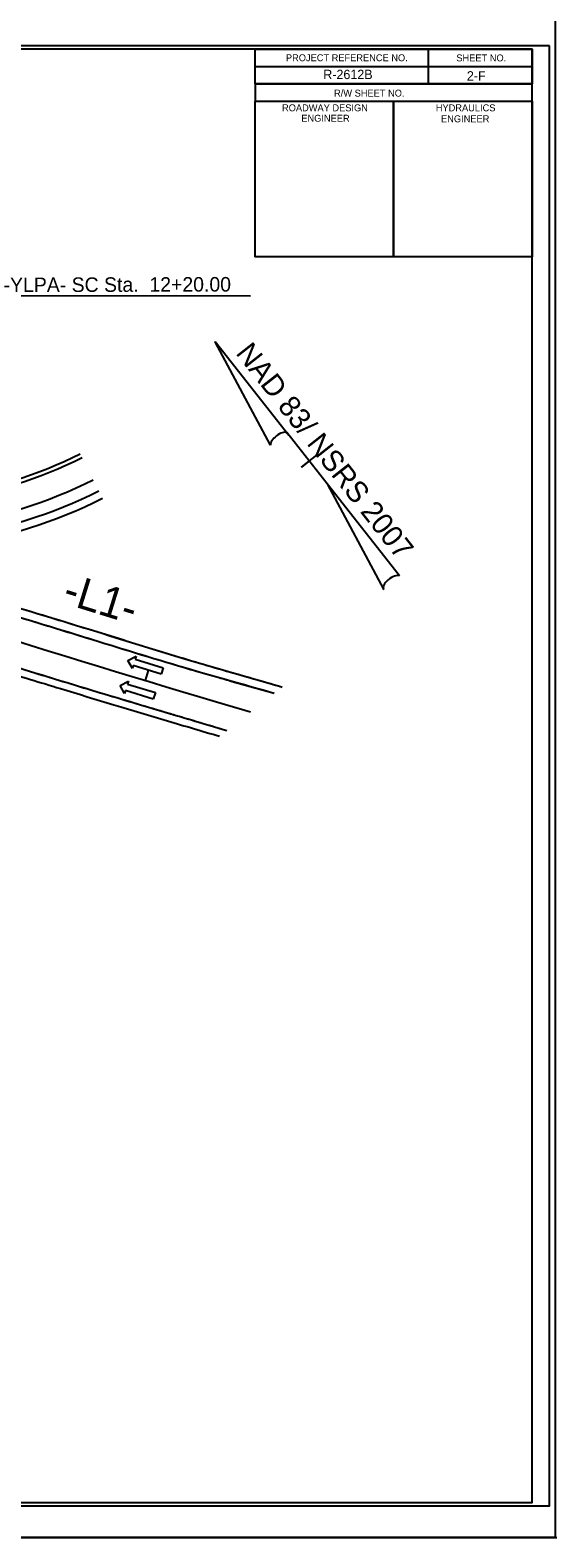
# Model space of a CAD drawing. Extents: x 573813 to 575363, y -54752 to -53123.
# Drawn here: x 574930.6 to 575006.7, y -54663.7 to -54445.8 of the extents above; entities that cross this region are included whole.
import ezdxf

# ---------------------------------------------------------------- set-up
doc = ezdxf.new("R2010")
doc.units = 0
for name, color, linetype in [('Exist CMT EOP', 7, 'Continuous'), ('Prop Conc 2ft 6in Curb and Gutter', 7, 'Continuous'), ('Prop EOT', 7, 'Continuous'), ('Prop Horizontal Alignment', 7, 'Continuous'), ('Prop Horizontal Alignment Station Label', 7, 'Continuous'), ('Prop Horizontal Alignment Tick Small', 7, 'Continuous'), ('Prop Lane Arrow CELL', 7, 'Continuous'), ('Prop North Arrow NAD83 for Plan Sheets CELL', 7, 'Continuous'), ('Prop Paved Shoulder', 7, 'Continuous'), ('Sheet Border Standard 30in CELL', 7, 'Continuous'), ('Sheet Cutting Line CELL', 7, 'Continuous'), ('Sheet Data Field CELL', 7, 'Continuous'), ('Sheet Plot Border Inside CELL', 7, 'Continuous'), ('Sheet Plot Border Outside CELL', 7, 'Continuous')]:
    doc.layers.add(name, color=color, linetype=linetype)

msp = doc.modelspace()

# ---------------------------------------------------------------- linework, layer by layer
at = {"layer": 'Exist CMT EOP'}
for points in [[(574813.01, -54490.03), (574824.43, -54494.19), (574838.57, -54499.09), (574853.67, -54504.44), (574867.6, -54509.43), (574881, -54513.82), (574895.19, -54518.43), (574909.35, -54523.04), (574924.04, -54527.74), (574938.33, -54532.12), (574953.44, -54536.77), (574966.78, -54540.64), (574967.02, -54540.71)], [(574811.75, -54491.02), (574824.51, -54495.58), (574838.71, -54500.46), (574852.94, -54505.5), (574866.51, -54510.15), (574881.43, -54515.23), (574895.44, -54519.84), (574909.74, -54524.51), (574923.56, -54528.9), (574937.86, -54533.31), (574952.04, -54537.64), (574965.88, -54541.6)], [(574805.27, -54496.11), (574807.81, -54497.02), (574821.91, -54502.08), (574836.06, -54507.09), (574850.12, -54511.98), (574865, -54517.11), (574878.57, -54521.65), (574892.88, -54526.42), (574907.53, -54531.21), (574921.45, -54535.6), (574935.95, -54540.08), (574950.27, -54544.38), (574959.02, -54546.99)], [(574926.29, -54538.29), (574934.97, -54540.93), (574950.47, -54545.6), (574957.97, -54547.82)]]:
    msp.add_spline(points, degree=3, dxfattribs=at)
at = {"layer": 'Prop Conc 2ft 6in Curb and Gutter'}
msp.add_arc((574908.9, -54449.03), 64.8, 278.4049, 296.5393, dxfattribs=at)
at = {"layer": 'Prop EOT'}
for radius in [65.4, 70.8]:
    msp.add_arc((574908.9, -54449.03), radius, 278.4049, 296.5393, dxfattribs=at)
for points in [[(574805.27, -54496.11), (574806.12, -54496.42), (574806.96, -54496.72), (574807.81, -54497.02), (574812.51, -54498.71), (574817.21, -54500.39), (574821.91, -54502.08), (574826.62, -54503.76), (574831.33, -54505.44), (574836.06, -54507.09), (574840.74, -54508.73), (574845.43, -54510.35), (574850.12, -54511.98), (574855.08, -54513.69), (574860.03, -54515.43), (574865, -54517.11), (574869.52, -54518.64), (574874.05, -54520.14), (574878.57, -54521.65), (574883.34, -54523.24), (574888.11, -54524.83), (574892.88, -54526.42), (574897.76, -54528.04), (574902.64, -54529.64), (574907.53, -54531.21), (574912.16, -54532.7), (574916.8, -54534.15), (574921.45, -54535.6), (574926.28, -54537.11), (574931.11, -54538.61), (574935.95, -54540.08), (574940.72, -54541.53), (574945.5, -54542.96), (574950.27, -54544.38), (574953.19, -54545.26), (574956.1, -54546.13), (574959.02, -54546.99)], [(574904.12, -54522.68), (574905.99, -54523.29), (574907.87, -54523.9), (574909.74, -54524.51), (574914.34, -54526.01), (574918.95, -54527.46), (574923.56, -54528.9), (574928.32, -54530.38), (574933.09, -54531.85), (574937.86, -54533.31), (574942.58, -54534.76), (574947.3, -54536.22), (574952.04, -54537.64), (574956.64, -54539.01), (574961.27, -54540.27), (574965.88, -54541.6)]]:
    msp.add_open_spline(points, degree=3, dxfattribs=at)
at = {"layer": 'Prop Horizontal Alignment'}
for centre, radius, start, end in [((574908.9, -54449.03), 69, 278.4049, 296.5393), ((575611.13, -52346.2), 2291.83, 251.5209, 253.55789)]:
    msp.add_arc(centre, radius, start, end, dxfattribs=at)
at = {"layer": 'Prop Horizontal Alignment Station Label'}
msp.add_line((574926.36, -54484.13), (574962.45, -54484.16), dxfattribs=at)
at = {"layer": 'Prop Horizontal Alignment Tick Small'}
msp.add_line((574947.26, -54539.78), (574947.7, -54538.34), dxfattribs=at)
at = {"layer": 'Prop Lane Arrow CELL'}
for p, q in [((574944.74, -54536.89), (574945.93, -54536.25)), ((574945.37, -54538.05), (574944.74, -54536.89)), ((574945.51, -54537.62), (574945.37, -54538.05)), ((574949.52, -54538.87), (574945.51, -54537.62)), ((574945.93, -54536.25), (574945.8, -54536.68)), ((574945.8, -54536.68), (574949.81, -54537.92)), ((574949.81, -54537.92), (574949.52, -54538.87)), ((574943.63, -54540.49), (574944.82, -54539.85)), ((574944.82, -54539.85), (574944.68, -54540.28)), ((574944.26, -54541.66), (574943.63, -54540.49)), ((574944.39, -54541.23), (574944.26, -54541.66)), ((574948.4, -54542.47), (574944.39, -54541.23)), ((574944.68, -54540.28), (574948.7, -54541.52)), ((574948.7, -54541.52), (574948.4, -54542.47))]:
    msp.add_line(p, q, dxfattribs=at)
at = {"layer": 'Prop North Arrow NAD83 for Plan Sheets CELL'}
for p, q in [((574957.35, -54490.8), (574957.34, -54490.81)), ((574957.35, -54490.8), (574957.34, -54490.81)), ((574965.33, -54505.76), (574957.34, -54490.81)), ((574957.35, -54490.8), (574967.99, -54504.33)), ((574973.51, -54511.35), (574967.68, -54503.93)), ((574967.99, -54504.33), (574967.69, -54503.95)), ((574969.81, -54508.94), (574972.07, -54507.16)), ((574969.79, -54508.96), (574969.78, -54508.97)), ((574970.8, -54508.17), (574969.79, -54508.96)), ((574973.51, -54511.35), (574981.66, -54526.58)), ((574983.99, -54524.65), (574973.51, -54511.35))]:
    msp.add_line(p, q, dxfattribs=at)
for centre, start_param, end_param in [((574966.61, -54504.98), 0.216388, 2.908219), ((574982.89, -54525.68), 0.201328, 3.141593)]:
    msp.add_ellipse(centre, major_axis=(1.2, 0.93), ratio=0.461098, start_param=start_param, end_param=end_param, dxfattribs=at)
at = {"layer": 'Prop Paved Shoulder'}
msp.add_arc((574908.9, -54449.03), 72, 278.4049, 296.5393, dxfattribs=at)
msp.add_open_spline([(574913.15, -54524.27), (574916.78, -54525.45), (574920.4, -54526.62), (574924.04, -54527.74), (574928.8, -54529.22), (574933.57, -54530.66), (574938.33, -54532.12), (574943.37, -54533.66), (574948.39, -54535.25), (574953.44, -54536.77), (574957.87, -54538.1), (574962.34, -54539.34), (574966.78, -54540.64), (574966.86, -54540.66), (574966.94, -54540.68), (574967.02, -54540.71)], degree=3, dxfattribs=at)
at = {"layer": 'Sheet Border Standard 30in CELL'}
for p, q in [((574988.13, -54448.55), (574988.13, -54453.55)), ((574963.12, -54451.05), (575003.13, -54451.05)), ((574963.12, -54453.55), (575003.13, -54453.55)), ((574963.12, -54453.55), (574963.12, -54456.05)), ((574963.12, -54453.55), (575003.13, -54453.55)), ((574983.13, -54456.05), (574983.13, -54478.54))]:
    msp.add_line(p, q, dxfattribs=at)
for points in [[(575003.13, -54448.54), (574703.13, -54448.54), (574703.13, -54658.54), (575003.13, -54658.54)], [(574963.12, -54448.54), (575003.13, -54448.54), (575003.13, -54453.55), (574963.12, -54453.55)], [(574963.12, -54456.05), (574983.13, -54456.05), (574983.13, -54478.55), (574963.12, -54478.55)], [(574983.13, -54456.05), (575003.13, -54456.05), (575003.13, -54478.55), (574983.13, -54478.55)]]:
    msp.add_lwpolyline(points, close=True, dxfattribs=at)
at = {"layer": 'Sheet Cutting Line CELL'}
for p, q in [((574669.73, -54663.54), (575006.53, -54663.54)), ((575006.71, -54663.66), (574669.73, -54663.66))]:
    msp.add_line(p, q, dxfattribs=at)
at = {"layer": 'Sheet Plot Border Inside CELL'}
msp.add_lwpolyline([(575005.63, -54448.03), (574672.33, -54448.03), (574672.33, -54659.05), (575005.63, -54659.05)], close=True, dxfattribs=at)
at = {"layer": 'Sheet Plot Border Outside CELL'}
msp.add_lwpolyline([(575006.53, -54443.54), (574669.73, -54443.54), (574669.73, -54663.54), (575006.53, -54663.54)], close=True, dxfattribs=at)

# ---------------------------------------------------------------- texts
at = {"layer": 'Prop Horizontal Alignment Station Label'}
for s, height, rotation, p in [('-YLPA- SC Sta.  12+20.00', 2.1, 0.159, (574926.77, -54483.65)), ('-L1-', 4.5, 342.7672, (574935.09, -54528.51))]:
    msp.add_text(s, height=height, rotation=rotation, dxfattribs=at).set_placement(p)
at = {"layer": 'Prop North Arrow NAD83 for Plan Sheets CELL'}
msp.add_text('NAD 83/ NSRS 2007', height=3.06, rotation=308.1792, dxfattribs=at).set_placement((574960.21, -54492.49))
at = {"layer": 'Sheet Border Standard 30in CELL'}
for s, p in [('PROJECT REFERENCE NO.', (574967.56, -54450.28)), ('SHEET NO.', (574992.19, -54450.3)), ('R/W SHEET NO.', (574974.52, -54455.39)), ('ROADWAY DESIGN', (574967, -54457.51)), ('HYDRAULICS', (574989.22, -54457.51)), ('ENGINEER', (574969.79, -54459.02)), ('ENGINEER', (574989.98, -54459.1))]:
    msp.add_text(s, height=1, dxfattribs=at).set_placement(p)
at = {"layer": 'Sheet Data Field CELL'}
for s, p in [('R-2612B  ', (574972.96, -54452.86)), ('2-F', (574993.71, -54453.07))]:
    msp.add_text(s, height=1.351, dxfattribs=at).set_placement(p)

doc.saveas('drawing.dxf')
